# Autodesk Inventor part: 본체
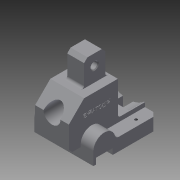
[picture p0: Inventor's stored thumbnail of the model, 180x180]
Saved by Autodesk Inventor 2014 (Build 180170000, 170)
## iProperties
Created: 2016-11
Part Number: 본체
Material: Generic
Document SubType Name: Modeling
Designer: user
Density: 1 g/cm^3
Appearance: Default
Author: user
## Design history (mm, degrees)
sketch "Sketch1"
  geometry: L1 (0, 0)-(0, 48); L2 (0, 48)-(-40, 48); L3 (-40, 48)-(-58, 30); L4 (-58, 30)-(-58, 0); L5 (-58, 0)-(0, 0)
  constraints: 10 end point, 2 parallel, 1 perpendicular, 1 vertical
  dimensions: "d8" = 58 distance between parallel lines of L4 L1; "d9" = 48 distance between parallel lines of L5 L2; "d10" = 30 distance of L3.end L4.end; "d103" = 18 distance from line of L2.end L4
extrude "Extrusion1" new body sketch "Sketch1" stored distance "d12" = 40; taper "d13" = 0 deg
sketch "Sketch6"
  geometry: L1 (-44, 8)-(32, 8); L2 (32, 8)-(32, -12); L3 (32, -12)-(-44, -12); L4 (-44, -12)-(-44, 8); L5 (-58, 0)-(-58, 30) reference; L6 (-40, 48)-(0, 48) reference; 1 further point
  constraints: 8 end point, 2 parallel, 1 horizontal, 1 perpendicular
  dimensions: "d19" = 20 distance of L1.end L2.end; "d20" = 76 distance of L2.end L3.end; "d21" = 90 distance between parallel lines of L2 L5; "d22" = 60 distance between parallel lines of L3 L6
extrude "Extrusion3" join sketch "Sketch6" stored distance "d23" = 70; taper "d24" = 0 deg
sketch "Sketch9"
  geometry: L1 (0, 0)-(15, 0); L2 (15, 0)-(15, 5); L3 (15, 5)-(0, 5); L4 (0, 5)-(0, 0); 1 further point
  constraints: 8 end point, 2 parallel, 1 horizontal, 1 perpendicular
  dimensions: "d29" = 5 distance of L3.end L1.start; "d30" = 15 distance of L2.end L3.end
extrude "Extrusion4" cut sketch "Sketch9" stored distance "d31" = 70; taper "d32" = 0 deg
mirror "Mirror1"
sketch "Sketch10"
  geometry: L1 (0, 8)-(32, 8) reference; L2 (32, 8)-(32, -12) reference; L3 (32, -12)-(-44, -12) reference; L4 (-44, -12)-(-44, 0) reference; L5 (-44, 0)-(-58, 0) reference; L6 (-58, 0)-(-58, 30) reference; L7 (-58, 30)-(-40, 48) reference; L8 (-40, 48)-(0, 48) reference; L9 (0, 48)-(0, 8) reference; L10 (32, 3)-(-44, 3) reference; L11 (-44, -12)-(-44, 3) reference; L12 (-44, 3)-(-18, 3); A1 r 13 centre (-31, 3) between (-18, 3) and (-44, 3); 1 further point
  constraints: 3 end point, 2 point on circle, 2 point on line, 1 centre point, 1 perpendicular, 1 tangent
  dimensions: "d33" = 26 diameter of A1
extrude "Extrusion5" join sketch "Sketch10" stored distance "d34" = 70; taper "d35" = 0 deg
sketch "Sketch11"
  geometry: L1 (-3, -44)-(12, -44) reference; L2 (12, -44)-(12, 32) reference; L3 (12, -41)-(5, -41); L4 (5, -41)-(5, -21); L5 (5, -21)-(12, -21); L6 (12, -21)-(12, -41); 1 further point
  constraints: 8 end point, 2 parallel, 1 horizontal, 1 perpendicular, 1 point on line
  dimensions: "d36" = 3 distance between parallel lines of L3 L1; "d37" = 20 distance between parallel lines of L5 L3; "d38" = 7 distance between parallel lines of L2 L4
extrude "Extrusion6" cut sketch "Sketch11" stored distance "d39" = 70; taper "d40" = 0 deg
chamfer "Chamfer1" distance "d41" = 4; stored, may be unused: second distance "d42" = 2, angle "d43" = 45 deg
sketch "Sketch12"
  geometry: L1 (0, 8)-(32, 8) reference; L2 (32, 8)-(32, -12) reference; L3 (32, -12)-(-21, -12) reference; L4 (-21, -12)-(-21, -5) reference; L5 (-21, -5)-(-41, -5) reference; L6 (-41, -5)-(-41, -12) reference; L7 (-41, -12)-(-44, -12) reference; L8 (-44, -12)-(-44, 0) reference; L9 (-44, 0)-(-54, 0) reference; L10 (-54, 0)-(-58, 4) reference; L11 (-58, 4)-(-58, 30) reference; L12 (-58, 30)-(-40, 48) reference; L13 (-40, 48)-(0, 48) reference; L14 (0, 48)-(0, 8) reference; L15 (0, 8)-(32, 8) reference; L16 (32, 8)-(32, -12) reference; L17 (32, -12)-(-21, -12) reference; L18 (-21, -12)-(-21, -5) reference; L19 (-21, -5)-(-41, -5) reference; L20 (-41, -5)-(-41, -12) reference; L21 (-41, -12)-(-44, -12) reference; L22 (-44, -12)-(-44, 0) reference; L23 (-44, 0)-(-54, 0) reference; L24 (-54, 0)-(-58, 4) reference; L25 (-58, 4)-(-58, 30) reference; L26 (-58, 30)-(-40, 48) reference; L27 (-40, 48)-(0, 48) reference; L28 (0, 48)-(0, 8) reference; L29 (0, 48)-(-40, 48) reference; L30 (-5, 48)-(-30, 48); L31 (-30, 48)-(-30, 78); L32 (-30, 78)-(-5, 78); L33 (-5, 78)-(-5, 48); 1 further point
  constraints: 8 end point, 2 parallel, 1 horizontal, 1 perpendicular, 1 point on line
  dimensions: "d44" = 25 distance of L31.end L32.end; "d45" = 90 distance between parallel lines of L3 L32; "d46" = 30 distance of L30.end L31.end (derived); "d102" = 5 distance between parallel lines of L14 L33
extrude "Extrusion7" join sketch "Sketch12" stored distance "d48" = 20; taper "d49" = 0 deg
chamfer "Chamfer2" distance "d50" = 4; stored, may be unused: second distance "d51" = 2, angle "d52" = 45 deg
sketch "Sketch13"
  geometry: L1 (55, 60)-(-15, 60) reference; L2 (55, 60)-(55, 45) reference; L3 (0, 48)-(40, 48) reference; C1 r 14.5 at (20, 18); 1 further point
  constraints: 1 centre point
  dimensions: "d53" = 29 diameter of C1; "d55" = 35 distance from line of C1.centre L2; "d56" = 30 distance from line of C1.centre L3
extrude "Extrusion8" cut sketch "Sketch13" distance "d57" = 7; taper "d58" = 0 deg
sketch "Sketch14"
  geometry: C1 r 14.5 at (0, 0) reference; C2 r 10 at (0, 0); 1 further point
  constraints: 1 centre point, 1 coincident
  dimensions: "d59" = 20 diameter of C2
extrude "Extrusion9" cut sketch "Sketch14" stored distance "d60" = 7; taper "d61" = 0 deg
chamfer "Chamfer3" distance "d62" = 1; stored, may be unused: second distance "d63" = 2, angle "d64" = 45 deg
sketch "Sketch15"
  geometry: L1 (-74, -30)-(-48, -30) reference; L2 (12, 32)-(12, -21) reference; C1 r 4 at (-65, -17.5); 1 further point
  constraints: 1 centre point
  dimensions: "d65" = 8 diameter of C1; "d66" = 12.5 distance from line of C1.centre L1; "d67" = 77 distance from line of C1.centre L2
extrude "Extrusion10" cut sketch "Sketch15" stored distance "d68" = 7; taper "d69" = 0 deg
chamfer "Chamfer4" distance "d70" = 1; stored, may be unused: second distance "d71" = 2, angle "d72" = 45 deg
fillet "Fillet1" dims "d73" = 5
fillet "Fillet2" dims "d74" = 3
sketch "Sketch16"
  geometry: C1 r 29 at (35, -42); C2 r 11 at (35, -42) reference; 1 further point
  constraints: 1 centre point, 1 concentric
  dimensions: "d75" = 58 diameter of C1
extrude "Extrusion11" cut sketch "Sketch16" distance "d76" = 18; taper "d77" = 0 deg
sketch "Sketch17"
  geometry: L1 (70, 0)-(0, 0) reference; L2 (29, 0)-(41, 0); L3 (41, 0)-(41, -17.5); L4 (41, -17.5)-(29, -17.5); L5 (29, -17.5)-(29, 0); 2 further points
  constraints: 8 end point, 2 parallel, 1 horizontal, 1 midpoint, 1 perpendicular, 1 point on line, 1 vertical alignment
  dimensions: "d78" = 12 distance of L3.end L4.end; "d79" = 17.5 distance of L4.end L2.start
extrude "Extrusion12" cut sketch "Sketch17" distance "d80" = 18; taper "d81" = 0 deg
fillet "Fillet3" dims "d82" = 3
chamfer "Chamfer5" distance "d83" = 5; stored, may be unused: second distance "d84" = 2, angle "d85" = 45 deg
sketch "Sketch18"
  geometry: L1 (0, 45.708)-(10, 45.708) reference; L2 (-50, 45.708)-(-40, 45.708) reference; L3 (-20, 13.708)-(-20, 49.368); 2 further points
  constraints: 2 end point, 1 perpendicular
  dimensions: "d86" = 18 distance from line of point (7.5, 27.708) L1; "d87" = 18 distance from line of point (-47.5, 27.708) L2; "d88" = 55 distance of point (7.5, 27.708) point (-47.5, 27.708); "d89" = 27.5 distance from line of point (-47.5, 27.708) L3; "d90" = 27.5 distance from line of point (7.5, 27.708) L3 (derived)
hole "Hole1" sketch "Sketch18" at (7.5, 27.708), (-47.5, 27.708) diameter "d91" = 3.242; stored, may be unused: countersink angle "d95" = 90 deg, drill point angle "d97" = 118 deg; dims "d92" = 20, "d93" = 4, "d94" = 2, "d96" = 8
sketch "Sketch19"
  geometry: L1 (-11, 0)-(-48, 0) reference; L2 (-48, 0)-(-48, -40) reference; 2 further points
  constraints: 1 other
  dimensions: "d98" = 25 distance from line of point (-30, -25) L1; "d99" = 18 distance from line of point (-30, -25) L2
emboss "Emboss1" sketch "Sketch19" dims "d100" = 0.5, "d101" = 0
body "Solid1"
node "Project Cut Edges3"
node "Project Cut Edges4"
node "Project Cut Edges5"
